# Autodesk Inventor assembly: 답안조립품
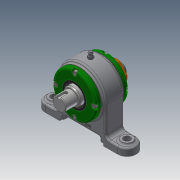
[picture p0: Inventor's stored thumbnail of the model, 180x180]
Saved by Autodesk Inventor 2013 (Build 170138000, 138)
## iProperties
Created: 2019-05
Part Number: 답안조립품
Document SubType Name: Assembly
Designer: user
Author: user
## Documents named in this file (13)
- C:\Users\user\Desktop\490504V1014\답안조립품.iam
- C:\Users\user\Desktop\490504V1014\본체.ipt
- C:\Users\user\Desktop\490504V1014\개스킷.ipt
- C:\Users\user\Desktop\490504V1014\그리스니플 M6.ipt
- 그리스니플  M6.ipt
- C:\Users\user\Desktop\490504V1014\그리스니플개스킷.ipt
- C:\Users\user\Desktop\490504V1014\베어링너트.ipt
- C:\Users\user\Desktop\490504V1014\볼트 M4.ipt
- C:\Users\user\Desktop\490504V1014\앵귤러 볼 베어링 7205.ipt
- C:\Users\user\Desktop\490504V1014\오일 실 28 40 5 B.ipt
- C:\Users\user\Desktop\490504V1014\축.ipt
- C:\Users\user\Desktop\490504V1014\칼라.ipt
- C:\Users\user\Desktop\490504V1014\커버.ipt
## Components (4 placed, 3 different names)
1. 개스킷:1
2. 그리스니플  M6:1
3. 그리스니플개스킷:1
4. 개스킷:2
